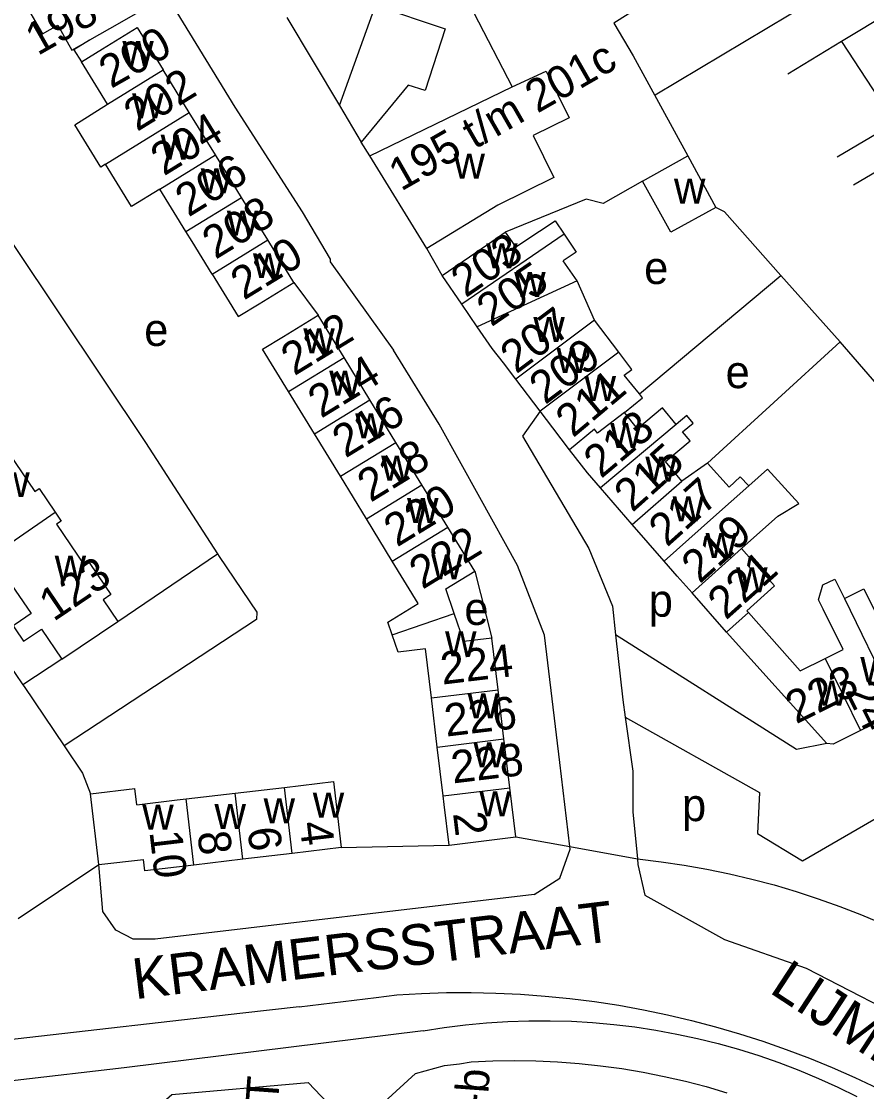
# Model space of a CAD drawing. Extents: x 159902 to 161769, y 383692 to 384875.
# Drawn here: x 160500.8 to 160604.7, y 384145.4 to 384277.1 of the extents above; entities that cross this region are included whole.
import ezdxf

# ---------------------------------------------------------------- set-up
doc = ezdxf.new("R2010")
doc.units = 0
for name, color, linetype in [('BLT_Basislijn', 7, 'Continuous'), ('BLT_Bebouwing', 7, 'Continuous'), ('BLT_Centroide', 7, 'Continuous'), ('BLT_Huisnummer', 7, 'Continuous'), ('BLT_Huisnummer_ tussenligend', 7, 'Continuous'), ('BLT_Huisnummer_reeks', 7, 'Continuous'), ('BLT_Onderverdeling_panden', 7, 'Continuous'), ('BLT_Straatnaam', 7, 'Continuous'), ('BLT_Straatnaam_verkleind', 7, 'Continuous'), ('BLT_Vlakafsluiter', 7, 'Continuous')]:
    doc.layers.add(name, color=color, linetype=linetype)

msp = doc.modelspace()

# ---------------------------------------------------------------- linework, layer by layer
at = {"layer": 'BLT_Basislijn'}
for p, q in [((160578.74, 384268.07), (160597.98, 384279.55)), ((160556.41, 384278.16), (160561.14, 384269.02)), ((160607.82, 384278.35), (160601.67, 384274.6)), ((160601.67, 384274.6), (160595.05, 384270.58)), ((160601.67, 384274.6), (160608.22, 384264.58)), ((160576.03, 384272.87), (160582.77, 384260.54)), ((160608.22, 384264.58), (160601.11, 384260.38)), ((160543.64, 384260.54), (160542.56, 384262.25)), ((160610.42, 384261.23), (160603.14, 384256.94)), ((160552.54, 384245.83), (160550.66, 384249.13)), ((160534.27, 384244.97), (160537.27, 384240.95)), ((160576.8, 384231.25), (160594.19, 384245.82)), ((160594.19, 384245.82), (160601.48, 384237.68)), ((160512.61, 384203.27), (160524.9, 384211.57)), ((160556.53, 384209.47), (160558.64, 384201.2)), ((160505.74, 384198.62), (160500.95, 384195.48)), ((160561.58, 384176.75), (160568.22, 384175.56)), ((160540.12, 384175.44), (160553.37, 384175.76)), ((160534.94, 384155.86), (160544.4, 384157.02)), ((160544.4, 384157.02), (160546.96, 384157.33)), ((160534.94, 384155.86), (160527.99, 384155.07)), ((160550.2, 384152.91), (160513.4, 384148.33)), ((160554.65, 384148.85), (160556.1, 384149.08))]:
    msp.add_line(p, q, dxfattribs=at)
for points in [[(160437.92, 384298.9), (160433.19, 384295.39), (160432.67, 384294.41), (160432.8, 384294.03), (160500, 384196.88), (160500.95, 384195.48)], [(160474.04, 384299.43), (160495.78, 384260.7), (160498.73, 384251.22), (160500, 384249.27), (160516.04, 384225.27), (160524.9, 384211.57)], [(160591.61, 384288.18), (160573.65, 384276.87), (160576.03, 384272.87)], [(160515.97, 384278.66), (160518.65, 384280.22), (160527, 384266.52), (160535.29, 384253.64), (160538.73, 384247.82), (160538.73, 384247.5), (160546.53, 384236.66)], [(160539.88, 384266.74), (160544.32, 384279.06), (160552.89, 384276.18), (160550.44, 384268.6), (160548.36, 384269.25), (160542.56, 384262.25)], [(160533.41, 384277.55), (160539.88, 384266.74)], [(160509.14, 384274.79), (160507.23, 384273.59), (160508.16, 384272.13)], [(160539.88, 384266.74), (160542.56, 384262.25)], [(160577.18, 384257.43), (160572.35, 384254.68), (160570.24, 384255.21), (160560.3, 384251.15)], [(160594.19, 384245.82), (160587.27, 384253.65), (160586.18, 384254.19)], [(160638.17, 384240.79), (160637, 384240.24), (160619.55, 384231.35), (160618.46, 384230.94), (160617.49, 384230.35), (160610.5, 384227.26), (160601.48, 384237.68)], [(160601.48, 384237.68), (160585.16, 384222.73)], [(160568.22, 384175.56), (160567.01, 384185.9), (160565.13, 384201.58), (160561.78, 384210.16), (160557.18, 384218.52), (160552.17, 384227.52), (160546.53, 384236.66)], [(160564.57, 384229.13), (160562.41, 384226.05), (160570.56, 384212.25), (160573.49, 384205.14), (160573.87, 384201.63)], [(160524.9, 384211.57), (160525.1, 384211.27), (160529.74, 384204.41), (160529.69, 384203.49), (160506.04, 384187.96)], [(160573.87, 384201.63), (160574.74, 384193.64), (160575.05, 384191.48)], [(160599.84, 384188.27), (160596.14, 384187.52), (160573.87, 384201.63)], [(160500.95, 384195.48), (160501.09, 384195.27), (160506.04, 384187.96)], [(160575.05, 384191.48), (160591.57, 384182.22), (160591.33, 384177.17), (160596.86, 384173.8), (160607.2, 384179.82), (160609.39, 384177.68)], [(160575.05, 384191.48), (160575.99, 384184.86), (160575.99, 384179.84), (160576.55, 384174.06)], [(160506.04, 384187.96), (160508.26, 384184.61), (160509.27, 384182.06)], [(160563.86, 384169.69), (160567.01, 384171.68), (160568.26, 384175.24), (160568.22, 384175.56)], [(160576.55, 384174.06), (160579.49, 384173.71), (160582.29, 384173.29), (160585.09, 384172.8), (160587.87, 384172.23), (160590.64, 384171.58), (160593.38, 384170.85), (160596.1, 384170.04), (160598.8, 384169.16), (160601.47, 384168.2), (160604.12, 384167.17), (160606.73, 384166.06), (160609.32, 384164.88), (160611.87, 384163.63), (160614.38, 384162.31), (160616.85, 384160.91), (160619.29, 384159.45), (160621.68, 384157.92), (160623.79, 384156.49)], [(160576.55, 384174.06), (160576.62, 384173.35), (160577.46, 384169.59), (160587.28, 384164.15), (160597.31, 384160.6), (160611.94, 384153.07)], [(160563.86, 384169.69), (160517.22, 384164.17), (160514.51, 384164.16), (160512.39, 384165.3), (160510.78, 384167.6), (160510.3, 384173.37)], [(160546.96, 384157.33), (160550, 384157.5), (160553.05, 384157.6), (160556.09, 384157.61), (160559.14, 384157.55), (160562.18, 384157.41), (160565.22, 384157.18), (160568.25, 384156.88), (160571.27, 384156.5), (160574.28, 384156.04), (160577.28, 384155.49), (160580.26, 384154.88), (160583.22, 384154.18), (160586.17, 384153.4), (160589.09, 384152.55), (160591.99, 384151.62), (160594.87, 384150.62), (160597.71, 384149.54), (160600.53, 384148.38), (160603.32, 384147.16), (160606.07, 384145.85), (160608.79, 384144.48)], [(160527.99, 384155.07), (160500, 384151.86), (160453.18, 384146)], [(160550.2, 384152.91), (160552.78, 384153.32), (160555.38, 384153.64), (160557.98, 384153.89), (160560.59, 384154.06), (160563.2, 384154.14), (160565.81, 384154.15), (160568.43, 384154.08), (160571.04, 384153.92), (160573.64, 384153.69), (160576.23, 384153.38), (160578.82, 384152.98), (160581.39, 384152.51), (160583.94, 384151.96), (160586.48, 384151.34), (160589, 384150.63), (160591.49, 384149.85), (160593.96, 384148.99), (160596.4, 384148.06), (160598.81, 384147.05), (160601.19, 384145.97), (160603.54, 384144.82)], [(160541.6, 384140.66), (160549.25, 384147.65), (160552.82, 384148.62), (160554.65, 384148.85)], [(160556.1, 384149.08), (160558.75, 384149.2), (160561.41, 384149.24), (160564.07, 384149.2), (160566.72, 384149.09), (160569.37, 384148.89), (160572.01, 384148.61), (160574.64, 384148.25), (160577.26, 384147.82), (160579.86, 384147.3), (160582.45, 384146.71), (160585.02, 384146.04), (160587.57, 384145.29)], [(160513.4, 384148.33), (160500, 384146.79), (160468.24, 384142.34), (160453.61, 384138.94), (160446.91, 384136.68), (160439.69, 384133.26), (160431.46, 384128.18), (160423.21, 384121.53)], [(160509.95, 384136.94), (160519.25, 384145.08), (160536.04, 384146.55), (160541.6, 384140.66)]]:
    msp.add_lwpolyline(points, dxfattribs=at)
at = {"layer": 'BLT_Bebouwing'}
for p, q in [((160511.37, 384266.92), (160508.16, 384272.13)), ((160521.42, 384265.89), (160518.21, 384271.12)), ((160543.64, 384260.54), (160561.14, 384269.02)), ((160524.64, 384260.67), (160521.42, 384265.89)), ((160527.85, 384255.44), (160524.64, 384260.67)), ((160550.66, 384249.13), (160543.64, 384260.54)), ((160577.18, 384257.43), (160582.77, 384260.54)), ((160582.77, 384260.54), (160586.18, 384254.19)), ((160521.01, 384251.24), (160517.8, 384256.46)), ((160531.06, 384250.21), (160527.85, 384255.44)), ((160566.42, 384252.55), (160567.52, 384250.9)), ((160554.94, 384242.32), (160552.54, 384245.83)), ((160556.85, 384239.52), (160554.94, 384242.32)), ((160540.46, 384235.74), (160537.27, 384240.95)), ((160543.65, 384230.52), (160540.46, 384235.74)), ((160564.57, 384229.13), (160561.58, 384233.06)), ((160536.81, 384226.34), (160533.62, 384231.55)), ((160546.84, 384225.3), (160543.65, 384230.52)), ((160540.01, 384221.12), (160536.81, 384226.34)), ((160550.04, 384220.09), (160546.84, 384225.3)), ((160585.16, 384222.73), (160582.02, 384220.54)), ((160543.2, 384215.9), (160540.01, 384221.12)), ((160553.23, 384214.87), (160550.04, 384220.09)), ((160575.92, 384215.21), (160572.02, 384219.7)), ((160546.39, 384210.69), (160543.2, 384215.9)), ((160556.53, 384209.47), (160553.23, 384214.87)), ((160579.86, 384210.67), (160575.92, 384215.21)), ((160549.58, 384205.47), (160546.39, 384210.69)), ((160552.97, 384207.29), (160556.53, 384209.47)), ((160554.01, 384204.25), (160552.97, 384207.29)), ((160587.5, 384201.94), (160583.27, 384206.8)), ((160555.2, 384200.79), (160554.01, 384204.25)), ((160587.5, 384201.94), (160590.21, 384204.36)), ((160505.74, 384198.62), (160512.61, 384203.27)), ((160503.25, 384202.3), (160505.74, 384198.62)), ((160599.84, 384188.27), (160587.5, 384201.94)), ((160558.64, 384201.2), (160555.2, 384200.79)), ((160559.4, 384194.84), (160558.64, 384201.2)), ((160551.2, 384193.85), (160550.48, 384199.88)), ((160560.13, 384188.81), (160559.4, 384194.84)), ((160551.92, 384187.82), (160551.2, 384193.85)), ((160608.76, 384192.18), (160604.01, 384189.87)), ((160560.85, 384182.78), (160560.13, 384188.81)), ((160552.65, 384181.8), (160551.92, 384187.82)), ((160527.07, 384182.14), (160533.12, 384182.85)), ((160521.02, 384181.43), (160527.07, 384182.14)), ((160561.58, 384176.75), (160560.85, 384182.78)), ((160553.37, 384175.76), (160561.58, 384176.75)), ((160540.12, 384175.44), (160534.07, 384174.73)), ((160510.3, 384173.37), (160515.77, 384173.98)), ((160528.02, 384174.01), (160521.97, 384173.3)), ((160534.07, 384174.73), (160528.02, 384174.01)), ((160521.97, 384173.3), (160515.93, 384172.59))]:
    msp.add_line(p, q, dxfattribs=at)
for points in [[(160501.93, 384278.02), (160503.35, 384275.54), (160505.23, 384276.61), (160506.97, 384273.54), (160509.14, 384274.79)], [(160515.97, 384278.66), (160511.62, 384276.18), (160509.14, 384274.79)], [(160508.16, 384272.13), (160510.74, 384273.72), (160514.99, 384276.35), (160518.21, 384271.12)], [(160561.14, 384269.02), (160565.32, 384270.95), (160568.14, 384265.22), (160563.73, 384263.06), (160566.28, 384257.87), (160559.37, 384254.49), (160550.66, 384249.13)], [(160511.11, 384259.51), (160510.54, 384259.16), (160507.35, 384264.36), (160511.37, 384266.92)], [(160517.8, 384256.46), (160514.3, 384254.31), (160511.11, 384259.51)], [(160586.18, 384254.19), (160580.67, 384251.14), (160577.18, 384257.43)], [(160560.3, 384251.15), (160561.1, 384250), (160561.57, 384249.31), (160562.59, 384250), (160566.42, 384252.55)], [(160524.23, 384246.01), (160521.77, 384250), (160521.01, 384251.24)], [(160534.27, 384244.97), (160531.19, 384250), (160531.06, 384250.21)], [(160552.54, 384245.83), (160556.67, 384248.65), (160558.65, 384250), (160560.3, 384251.15)], [(160567.52, 384250.9), (160569, 384248.71), (160567.41, 384247.64)], [(160569.12, 384245.18), (160567.41, 384247.64)], [(160524.23, 384246.01), (160527.43, 384240.78), (160530.01, 384242.36), (160534.27, 384244.97)], [(160571.28, 384240.35), (160569.12, 384245.18)], [(160533.62, 384231.55), (160530.43, 384236.77), (160533.01, 384238.34), (160537.27, 384240.95)], [(160561.58, 384233.06), (160560.07, 384235.08), (160558.67, 384236.86), (160556.85, 384239.52)], [(160574.25, 384236.39), (160571.28, 384240.35)], [(160576.8, 384231.25), (160574.93, 384233.57), (160575.85, 384234.26), (160574.25, 384236.39)], [(160574.96, 384228.99), (160577.18, 384230.78), (160576.8, 384231.25)], [(160568.21, 384224.38), (160566.14, 384227.07), (160564.57, 384229.13)], [(160581.33, 384227.51), (160579.62, 384229.55), (160576.55, 384226.97), (160574.96, 384228.99)], [(160582.02, 384220.54), (160580, 384222.94), (160583.03, 384225.48), (160582.1, 384226.59), (160583.4, 384227.68), (160582.62, 384228.61), (160581.33, 384227.51)], [(160498.75, 384225.79), (160499.44, 384224.77), (160498.93, 384224.42), (160500, 384222.84), (160502.42, 384219.25), (160502.95, 384219.61), (160504.91, 384216.71)], [(160572.02, 384219.7), (160570.42, 384221.53), (160568.21, 384224.38)], [(160585.16, 384222.73), (160587.83, 384219.8), (160589.21, 384221.06), (160590.24, 384219.94)], [(160589.35, 384212.23), (160593.81, 384216.21), (160596.39, 384217.79), (160592.55, 384222), (160590.24, 384219.94)], [(160504.91, 384216.71), (160505.64, 384215.62), (160505.09, 384215.24), (160508.54, 384210.15), (160509.1, 384210.53), (160511.08, 384207.6)], [(160590.21, 384204.36), (160590, 384204.59), (160593.43, 384207.66), (160589.35, 384212.23)], [(160497.12, 384211.37), (160499.99, 384207.12), (160501.96, 384204.23), (160500, 384202.91), (160499.74, 384202.73), (160500, 384202.35), (160501, 384200.84), (160503.25, 384202.3)], [(160583.27, 384206.8), (160581.46, 384208.83), (160579.86, 384210.67)], [(160599.65, 384198.71), (160601.88, 384199.81), (160599.42, 384204.78), (160598.84, 384205.94), (160599.38, 384207.76), (160600.84, 384208.48), (160602.03, 384206.07)], [(160511.08, 384207.6), (160511.75, 384206.6), (160510.84, 384205.91), (160512.61, 384203.27)], [(160602.03, 384206.07), (160604.42, 384207.26), (160606.86, 384202.33), (160609.28, 384203.53)], [(160546.38, 384201.61), (160545.84, 384203.19), (160549.58, 384205.47)], [(160590.21, 384204.36), (160596.57, 384197.18), (160599.65, 384198.71)], [(160550.48, 384199.88), (160547.11, 384199.48), (160546.38, 384201.61)], [(160604.01, 384189.87), (160600.65, 384188.18), (160599.84, 384188.27)], [(160533.12, 384182.85), (160539.16, 384183.56), (160539.54, 384180.4), (160540.12, 384175.44)], [(160509.27, 384182.06), (160514.73, 384182.7)], [(160510.3, 384173.37), (160509.27, 384182.06)], [(160514.97, 384180.72), (160514.73, 384182.7)], [(160553.37, 384175.76), (160552.77, 384180.73), (160552.65, 384181.8)], [(160514.97, 384180.72), (160519.93, 384181.3), (160521.02, 384181.43)], [(160515.93, 384172.59), (160515.77, 384173.98)]]:
    msp.add_lwpolyline(points, dxfattribs=at)
at = {"layer": 'BLT_Onderverdeling_panden'}
for p, q in [((160511.37, 384266.92), (160518.21, 384271.12)), ((160511.11, 384259.51), (160521.42, 384265.89)), ((160517.8, 384256.46), (160524.64, 384260.67)), ((160521.01, 384251.24), (160527.85, 384255.44)), ((160524.23, 384246.01), (160531.06, 384250.21)), ((160567.52, 384250.9), (160554.94, 384242.32)), ((160571.28, 384240.35), (160561.58, 384233.06)), ((160533.62, 384231.55), (160540.46, 384235.74)), ((160574.25, 384236.39), (160564.57, 384229.13)), ((160536.81, 384226.34), (160543.65, 384230.52)), ((160581.33, 384227.51), (160572.02, 384219.7)), ((160540.01, 384221.12), (160546.84, 384225.3)), ((160543.2, 384215.9), (160550.04, 384220.09)), ((160575.92, 384215.21), (160582.02, 384220.54)), ((160585.91, 384216.08), (160590.24, 384219.94)), ((160579.86, 384210.67), (160585.91, 384216.08)), ((160546.39, 384210.69), (160553.23, 384214.87)), ((160583.27, 384206.8), (160589.35, 384212.23)), ((160602.03, 384206.07), (160608.76, 384192.18)), ((160546.38, 384201.61), (160554.01, 384204.25)), ((160599.65, 384198.71), (160604.01, 384189.87)), ((160551.2, 384193.85), (160559.4, 384194.84)), ((160551.92, 384187.82), (160560.13, 384188.81)), ((160534.07, 384174.73), (160533.12, 384182.85)), ((160528.02, 384174.01), (160527.07, 384182.14)), ((160552.65, 384181.8), (160560.85, 384182.78)), ((160521.97, 384173.3), (160521.02, 384181.43))]:
    msp.add_line(p, q, dxfattribs=at)
for points in [[(160569.12, 384245.18), (160556.85, 384239.52)], [(160574.96, 384228.99), (160571.65, 384226.43), (160571.28, 384226.91), (160568.21, 384224.38)], [(160497.12, 384211.37), (160500, 384213.32), (160504.91, 384216.71)]]:
    msp.add_lwpolyline(points, dxfattribs=at)
at = {"layer": 'BLT_Vlakafsluiter'}
for p, q in [((160568.22, 384175.56), (160576.55, 384174.06)), ((160500.37, 384166.74), (160510.3, 384173.37))]:
    msp.add_line(p, q, dxfattribs=at)

# ---------------------------------------------------------------- texts
at = {"layer": 'BLT_Centroide'}
for s, p in [('w', (160513.18, 384271.62)), ('w', (160514.39, 384265.16)), ('w', (160517.89, 384260.09)), ('w', (160553.93, 384257.75)), ('w', (160522.82, 384255.94)), ('w', (160581.05, 384254.67)), ('w', (160526.04, 384250.72)), ('w', (160557.95, 384246.72)), ('w', (160529.25, 384245.5)), ('e', (160577.38, 384244.78)), ('w', (160561.39, 384243.19)), ('e', (160515.87, 384237.16)), ('w', (160563.75, 384237.66)), ('w', (160535.45, 384236.25)), ('w', (160566.6, 384233.84)), ('e', (160587.4, 384231.97)), ('w', (160538.64, 384231.03)), ('w', (160570.05, 384230.38)), ('w', (160541.83, 384225.81)), ('w', (160573.2, 384224.62)), ('w', (160545.02, 384220.59)), ('w', (160577.53, 384220.47)), ('w', (160497.92, 384218.56)), ('w', (160548.21, 384215.38)), ('w', (160580.88, 384215.59)), ('w', (160584.94, 384211.06)), ('w', (160504.86, 384208.3)), ('w', (160551.19, 384208.45)), ('w', (160588.7, 384206.84)), ('p', (160577.94, 384203.85)), ('e', (160555.26, 384202.84)), ('w', (160552.89, 384198.97)), ('w', (160603.98, 384195.81)), ('w', (160598.54, 384192.92)), ('w', (160555.66, 384191.34)), ('w', (160556.38, 384185.31)), ('w', (160536.61, 384179.14)), ('w', (160557.11, 384179.28)), ('p', (160582.03, 384178.7)), ('w', (160515.63, 384177.66)), ('w', (160524.52, 384177.72)), ('w', (160530.56, 384178.44))]:
    msp.add_text(s, height=4, dxfattribs=at).set_placement(p)
at = {"layer": 'BLT_Huisnummer'}
for s, rotation, p in [('200', 29.6056, (160511.8, 384268.77)), ('204', 31.5696, (160518.29, 384258.01)), ('210', 31.4538, (160528.13, 384242.73)), ('203', 34.3174, (160555.41, 384243.02)), ('212', 31.4614, (160534.33, 384233.42)), ('207', 36.8917, (160561.64, 384233.65)), ('211', 40.0282, (160568.63, 384225.79)), ('216', 31.459, (160540.63, 384223.3)), ('215', 41.7607, (160575.93, 384216.6)), ('220', 31.4628, (160546.97, 384212.35)), ('222', 31.4628, (160550.1, 384207.14)), ('221', 41.7624, (160587.44, 384203.35)), ('224', 6.8455, (160552.55, 384195.49)), ('223', 26.2872, (160596.07, 384190.59)), ('24', 296.3317, (160602.03, 384194.73)), ('228', 6.8395, (160553.86, 384183.33)), ('2', 276.8451, (160553.86, 384179.66)), ('4', 276.709, (160534.97, 384178.49)), ('10', 276.709, (160516.51, 384177.38))]:
    msp.add_text(s, height=4, rotation=rotation, dxfattribs=at).set_placement(p)
at = {"layer": 'BLT_Huisnummer_ tussenligend'}
for s, rotation, p in [('202', 31.5696, (160514.99, 384263.47)), ('206', 31.5663, (160521.32, 384252.95)), ('208', 31.5663, (160524.64, 384247.74)), ('205', 34.3174, (160558.57, 384239.44)), ('209', 36.8917, (160565.2, 384229.86)), ('214', 31.4614, (160537.64, 384228.19)), ('213', 40.0282, (160572.08, 384220.76)), ('218', 31.459, (160543.72, 384217.85)), ('217', 41.7607, (160580.19, 384212.33)), ('219', 41.7607, (160584.22, 384207.83)), ('226', 6.8455, (160553.03, 384189.09)), ('6', 276.709, (160528.57, 384177.78)), ('8', 276.709, (160522.41, 384177.3))]:
    msp.add_text(s, height=4, rotation=rotation, dxfattribs=at).set_placement(p)
at = {"layer": 'BLT_Huisnummer_reeks'}
for s, rotation, p in [('198-a-b', 29.6056, (160502.76, 384272.81)), ('195 t/m 201c', 29.7782, (160547.47, 384256.13)), ('123', 34.0772, (160504.72, 384203.18)), ('5-a-b', 85.8546, (160557.51, 384135.67))]:
    msp.add_text(s, height=4, rotation=rotation, dxfattribs=at).set_placement(p)
at = {"layer": 'BLT_Straatnaam'}
for s, rotation, p in [('KRAMERSSTRAAT', 6.9378, (160514.74, 384156.78)), ('LIJMBEEKSTRAAT', 326.785, (160592.64, 384157.69))]:
    msp.add_text(s, height=4.9999, rotation=rotation, dxfattribs=at).set_placement(p)
at = {"layer": 'BLT_Straatnaam_verkleind'}
msp.add_text('CHRISTINA BAKKER-VAN BOSSESTRAAT', height=4, rotation=85.7906, dxfattribs=at).set_placement((160524.8, 384041.61))

doc.saveas('drawing.dxf')
